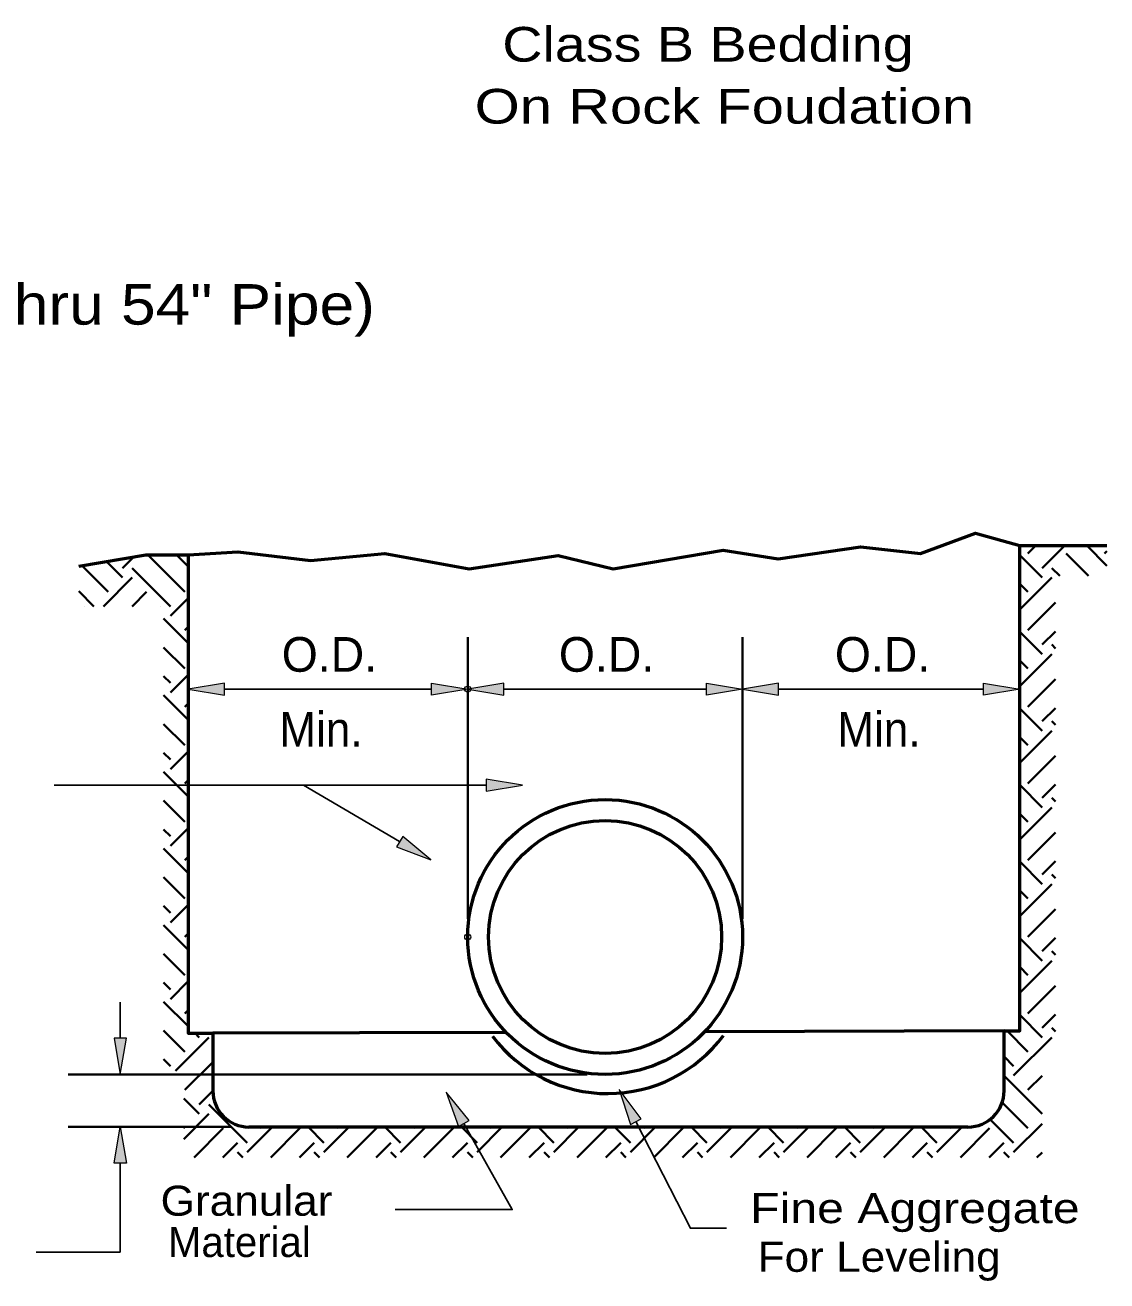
# Model space of a CAD drawing. Extents: x 36.1 to 71.5, y 0.2 to 22.2.
# Drawn here: x 46.27 to 51.06, y 10.72 to 16.28 of the extents above; entities that cross this region are included whole.
import ezdxf

# ---------------------------------------------------------------- set-up
doc = ezdxf.new("R2010")
doc.units = 0
doc.header["$LTSCALE"] = 0.053
doc.header["$PDMODE"] = 32
doc.header["$PDSIZE"] = 0.0265
for name, color, linetype, lineweight in [('1', 7, 'Continuous', 35), ('3', 7, 'Continuous', 25), ('6', 7, 'Continuous', 13)]:
    doc.layers.add(name, color=color, linetype=linetype, lineweight=lineweight)

msp = doc.modelspace()

# ---------------------------------------------------------------- hatches: boundary and pattern name
at = {"layer": '1'}
for points in [[(47.14958, 13.31667), (47.14958, 13.37), (46.98958, 13.34325), (46.98958, 13.34325)], [(48.06725, 13.31667), (48.06725, 13.37), (48.22725, 13.34325), (48.22725, 13.34325)], [(48.38725, 13.31667), (48.38725, 13.37), (48.22725, 13.34325), (48.22725, 13.34325)], [(49.2845, 13.31667), (49.2845, 13.37), (49.4445, 13.34325), (49.4445, 13.34325)], [(49.6045, 13.31667), (49.6045, 13.37), (49.4445, 13.34325), (49.4445, 13.34325)], [(50.51225, 13.31667), (50.51225, 13.37), (50.67225, 13.34325), (50.67225, 13.34325)]]:
    msp.add_hatch(color=256, dxfattribs=at).paths.add_polyline_path(points)
at = {"layer": '3'}
for points in [[(48.30958, 12.94433), (48.30958, 12.891), (48.46958, 12.91767), (48.46958, 12.91767)], [(47.93925, 12.69067), (47.91225, 12.64467), (48.06383, 12.5865), (48.06383, 12.5865)], [(46.71525, 11.79633), (46.66192, 11.79633), (46.68858, 11.63633), (46.68858, 11.63633)], [(48.18667, 11.40533), (48.23317, 11.4315), (48.13142, 11.55775), (48.13142, 11.55775)], [(48.94775, 11.41517), (48.99508, 11.4395), (48.89858, 11.56967), (48.89858, 11.56967)], [(46.71525, 11.24342), (46.66192, 11.24342), (46.68858, 11.40342), (46.68858, 11.40342)]]:
    msp.add_hatch(color=256, dxfattribs=at).paths.add_polyline_path(points)

# ---------------------------------------------------------------- linework, layer by layer
at = {"layer": '1'}
for p, q in [((50.70817, 13.94325), (50.74433, 13.97942)), ((50.77183, 13.8795), (50.87167, 13.97942)), ((51.05833, 13.89), (50.96908, 13.97942)), ((46.69892, 13.83717), (46.62742, 13.90858)), ((46.69892, 13.8795), (46.74817, 13.92883)), ((46.97475, 13.7735), (46.81033, 13.93783)), ((46.98958, 13.88583), (46.93758, 13.93783)), ((50.77183, 13.83717), (50.67225, 13.93675)), ((50.97675, 13.84433), (50.87792, 13.94325)), ((51.04758, 13.94325), (51.05833, 13.95392)), ((46.63525, 13.7735), (46.51842, 13.89033)), ((46.911, 13.70983), (46.74133, 13.8795)), ((50.8495, 13.84433), (50.81425, 13.8795)), ((46.61342, 13.70933), (46.74133, 13.83717)), ((50.67225, 13.69517), (50.81425, 13.83717)), ((50.70817, 13.7735), (50.67225, 13.8095)), ((46.57158, 13.70983), (46.50442, 13.77692)), ((46.74083, 13.70933), (46.805, 13.7735)), ((46.911, 13.66742), (46.98958, 13.74592)), ((46.52858, 13.70933), (46.52917, 13.70983)), ((46.86808, 13.70933), (46.86858, 13.70983)), ((50.70817, 13.60383), (50.83058, 13.72625)), ((46.98958, 13.5465), (46.88058, 13.65533)), ((46.97475, 13.60383), (46.98958, 13.61867)), ((48.22725, 12.325), (48.22725, 13.57375)), ((49.4445, 12.325), (49.4445, 13.57375)), ((50.77183, 13.49767), (50.67225, 13.59733)), ((50.77183, 13.54017), (50.83058, 13.59892)), ((46.97475, 13.43417), (46.88058, 13.52808)), ((50.83058, 13.52375), (50.81425, 13.54017)), ((50.67225, 13.35575), (50.81425, 13.49767)), ((50.70817, 13.43417), (50.67225, 13.47008)), ((46.911, 13.3705), (46.88058, 13.40083)), ((46.911, 13.328), (46.98958, 13.4065)), ((50.70817, 13.26442), (50.83058, 13.38683)), ((46.98958, 13.207), (46.88058, 13.31592)), ((46.97475, 13.26442), (46.98958, 13.27925)), ((50.77183, 13.15825), (50.67225, 13.25792)), ((50.77183, 13.20075), (50.83058, 13.2595)), ((46.97475, 13.09475), (46.88058, 13.18867)), ((50.83058, 13.18433), (50.81425, 13.20075)), ((50.67225, 13.01633), (50.81425, 13.15825)), ((50.70817, 13.09475), (50.67225, 13.13067)), ((46.911, 13.031), (46.88058, 13.06142)), ((46.911, 12.98858), (46.98958, 13.06708)), ((50.70817, 12.925), (50.83058, 13.0475)), ((46.98958, 12.86758), (46.88058, 12.9765)), ((46.97475, 12.925), (46.98958, 12.93983)), ((50.77183, 12.81883), (50.67225, 12.9185)), ((50.77183, 12.86133), (50.83058, 12.92008)), ((50.83058, 12.84483), (50.81425, 12.86133)), ((46.97475, 12.75525), (46.88058, 12.84925)), ((50.67225, 12.67683), (50.81425, 12.81883)), ((50.70817, 12.75525), (50.67225, 12.79125)), ((46.911, 12.69158), (46.88058, 12.722)), ((46.911, 12.64917), (46.98958, 12.72767)), ((50.70817, 12.58558), (50.83058, 12.70808)), ((46.98958, 12.52817), (46.88058, 12.63717)), ((46.98958, 12.52817), (46.88058, 12.63717)), ((46.97475, 12.58558), (46.98958, 12.60042)), ((50.77183, 12.4795), (50.67225, 12.57908)), ((50.77183, 12.52192), (50.83058, 12.58067)), ((50.83058, 12.5055), (50.81425, 12.52192)), ((46.97475, 12.41583), (46.88058, 12.50983)), ((50.67225, 12.3375), (50.81425, 12.4795)), ((50.67225, 12.3375), (50.81425, 12.4795)), ((50.70817, 12.41583), (50.67225, 12.45183)), ((46.911, 12.35217), (46.88058, 12.38258)), ((46.911, 12.30975), (46.98958, 12.38825)), ((50.70817, 12.24617), (50.83058, 12.36858)), ((46.98958, 12.18883), (46.88058, 12.29767)), ((46.97475, 12.24617), (46.98958, 12.261)), ((50.77183, 12.14008), (50.67225, 12.23967)), ((50.77183, 12.1825), (50.83058, 12.24125)), ((46.97475, 12.0765), (46.88058, 12.1705)), ((50.67225, 11.99808), (50.81425, 12.14008)), ((50.83058, 12.16608), (50.81425, 12.1825)), ((50.70817, 12.0765), (50.67225, 12.11242)), ((46.911, 12.01283), (46.88058, 12.04317)), ((46.911, 11.97033), (46.98958, 12.04892)), ((50.70817, 11.90675), (50.83058, 12.02917)), ((46.98958, 11.84942), (46.88058, 11.95825)), ((46.97475, 11.90675), (46.98958, 11.92158)), ((50.77183, 11.80058), (50.67225, 11.90025)), ((50.77183, 11.84308), (50.83058, 11.90183)), ((46.97475, 11.73708), (46.88058, 11.831)), ((46.93283, 11.65267), (47.08075, 11.80058)), ((47.03825, 11.80058), (47.02008, 11.81883)), ((50.70817, 11.73708), (50.616, 11.82917)), ((50.64458, 11.63092), (50.81425, 11.80058)), ((50.83058, 11.82675), (50.81425, 11.84308)), ((46.911, 11.67342), (46.88058, 11.70383)), ((46.97475, 11.56733), (47.0985, 11.69108)), ((50.64458, 11.67342), (50.603, 11.715)), ((50.77125, 11.46183), (50.603, 11.63017)), ((50.70817, 11.56733), (50.77125, 11.63042)), ((47.03825, 11.46117), (46.96967, 11.52983)), ((47.03825, 11.50367), (47.0985, 11.56383)), ((46.96967, 11.35025), (47.08075, 11.46117)), ((47.2505, 11.33392), (47.08075, 11.50367)), ((50.70817, 11.39767), (50.59433, 11.5115)), ((50.64458, 11.33392), (50.54133, 11.43717)), ((50.64458, 11.2915), (50.77125, 11.41817)), ((46.97475, 11.39767), (46.96967, 11.4025)), ((47.01517, 11.26833), (47.14442, 11.39767)), ((47.2505, 11.2915), (47.36233, 11.40342)), ((47.31417, 11.39767), (47.30825, 11.40342)), ((47.35458, 11.26833), (47.48383, 11.39767)), ((47.58992, 11.33392), (47.52042, 11.40342)), ((47.58992, 11.2915), (47.70167, 11.40342)), ((47.65358, 11.39767), (47.64767, 11.40342)), ((47.69392, 11.26833), (47.82325, 11.39767)), ((47.92925, 11.33392), (47.85983, 11.40342)), ((47.92925, 11.2915), (48.04108, 11.40342)), ((47.99292, 11.39767), (47.98708, 11.40342)), ((48.03342, 11.26833), (48.16258, 11.39767)), ((48.26867, 11.33392), (48.19925, 11.40342)), ((48.26867, 11.2915), (48.3805, 11.40342)), ((48.33225, 11.39767), (48.3265, 11.40342)), ((48.37283, 11.26833), (48.50192, 11.39767)), ((48.60808, 11.33392), (48.53867, 11.40342)), ((48.60808, 11.2915), (48.71992, 11.40342)), ((48.67167, 11.39767), (48.66592, 11.40342)), ((48.71225, 11.26833), (48.84142, 11.39767)), ((48.94758, 11.33392), (48.87808, 11.40342)), ((48.94758, 11.2915), (49.05925, 11.40342)), ((49.01108, 11.39767), (49.00533, 11.40342)), ((49.05158, 11.26833), (49.18083, 11.39767)), ((49.28692, 11.33392), (49.2175, 11.40342)), ((49.28692, 11.2915), (49.39875, 11.40342)), ((49.3505, 11.39767), (49.34475, 11.40342)), ((49.391, 11.26833), (49.52025, 11.39767)), ((49.62633, 11.33392), (49.55692, 11.40342)), ((49.62633, 11.2915), (49.73817, 11.40342)), ((49.68992, 11.39767), (49.68417, 11.40342)), ((49.7305, 11.26833), (49.85958, 11.39767)), ((49.96575, 11.33392), (49.89633, 11.40342)), ((49.96575, 11.2915), (50.07758, 11.40342)), ((50.02933, 11.39767), (50.02358, 11.40342)), ((50.06992, 11.26833), (50.199, 11.39767)), ((50.30517, 11.33392), (50.23575, 11.40342)), ((50.30517, 11.2915), (50.41692, 11.40342)), ((50.36875, 11.39767), (50.363, 11.40342)), ((50.40925, 11.26833), (50.5385, 11.39767)), ((47.14242, 11.26833), (47.208, 11.33392)), ((47.48183, 11.26833), (47.54742, 11.33392)), ((47.82125, 11.26833), (47.88683, 11.33392)), ((48.16058, 11.26833), (48.22625, 11.33392)), ((48.50008, 11.26833), (48.56567, 11.33392)), ((48.8395, 11.26833), (48.90508, 11.33392)), ((49.17892, 11.26833), (49.2445, 11.33392)), ((49.51825, 11.26833), (49.58392, 11.33392)), ((49.85767, 11.26833), (49.92325, 11.33392)), ((50.19717, 11.26833), (50.26275, 11.33392)), ((50.53658, 11.26833), (50.60217, 11.33392)), ((47.23117, 11.26833), (47.208, 11.2915)), ((47.57058, 11.26833), (47.54742, 11.2915)), ((47.90992, 11.26833), (47.88683, 11.2915)), ((48.24942, 11.26833), (48.22625, 11.2915)), ((48.58883, 11.26833), (48.56567, 11.2915)), ((48.92825, 11.26833), (48.90508, 11.2915)), ((49.26758, 11.26833), (49.2445, 11.2915)), ((49.607, 11.26833), (49.58392, 11.2915)), ((49.9465, 11.26833), (49.92325, 11.2915)), ((50.28592, 11.26833), (50.26275, 11.2915)), ((50.62525, 11.26833), (50.60217, 11.2915)), ((50.74867, 11.26833), (50.77125, 11.291))]:
    msp.add_line(p, q, dxfattribs=at)
at = {"layer": '1', "lineweight": 13}
for p, q in [((48.22725, 12.325), (48.22725, 13.57375)), ((49.4445, 12.325), (49.4445, 13.57375)), ((50.67225, 13.39967), (50.67225, 13.57375)), ((46.98958, 13.26333), (46.98958, 13.11292))]:
    msp.add_line(p, q, dxfattribs=at)
at = {"layer": '1', "lineweight": 25}
for p, q in [((47.14958, 13.34333), (48.06725, 13.34333)), ((48.38725, 13.34333), (49.2845, 13.34333)), ((49.6045, 13.34333), (50.51225, 13.34333))]:
    msp.add_line(p, q, dxfattribs=at)
at = {"layer": '1', "lineweight": 53}
for p, q in [((48.39767, 11.82275), (47.0985, 11.81883)), ((50.603, 11.82917), (49.2765, 11.82542)), ((47.2585, 11.40342), (50.443, 11.40342))]:
    msp.add_line(p, q, dxfattribs=at)
for points in [[(46.98958, 13.93783), (47.20858, 13.95092), (47.53108, 13.91325), (47.86083, 13.94333), (48.23342, 13.87575), (48.62758, 13.93583), (48.87125, 13.87575), (49.3585, 13.95842), (49.60225, 13.92083), (49.96767, 13.97342), (50.23292, 13.94333), (50.4765, 14.03358), (50.67225, 13.97942)], [(50.603, 11.56342), (50.603, 11.82917), (50.67225, 11.82917), (50.67225, 13.97942), (51.05833, 13.97942)], [(46.50442, 13.888), (46.8015, 13.93783), (46.98958, 13.93783), (46.98958, 11.81883), (47.0985, 11.81883), (47.0985, 11.56342)]]:
    msp.add_lwpolyline(points, dxfattribs=at)
at = {"layer": '1', "lineweight": 13}
for points in [[(47.14958, 13.31667), (47.14958, 13.37), (46.98958, 13.34325), (46.98958, 13.34325)], [(48.06725, 13.31667), (48.06725, 13.37), (48.22725, 13.34325), (48.22725, 13.34325)], [(48.38725, 13.31667), (48.38725, 13.37), (48.22725, 13.34325), (48.22725, 13.34325)], [(49.2845, 13.31667), (49.2845, 13.37), (49.4445, 13.34325), (49.4445, 13.34325)], [(49.6045, 13.31667), (49.6045, 13.37), (49.4445, 13.34325), (49.4445, 13.34325)], [(50.51225, 13.31667), (50.51225, 13.37), (50.67225, 13.34325), (50.67225, 13.34325)]]:
    msp.add_lwpolyline(points, close=True, dxfattribs=at)
at = {"layer": '1', "lineweight": 53}
for radius in [0.60865, 0.51601]:
    msp.add_circle((48.83584, 12.24511), radius, dxfattribs=at)
for centre, radius, start, end in [((48.84725, 12.1908), 0.63944, 217.05519, 323.28444), ((47.25846, 11.5634), 0.16, 180, 270), ((50.44299, 11.5634), 0.16, 270, 0)]:
    msp.add_arc(centre, radius, start, end, dxfattribs=at)
at = {"layer": '3'}
for p, q in [((48.30958, 12.91767), (46.39558, 12.91767)), ((47.92575, 12.66758), (47.50017, 12.91767)), ((46.68858, 11.7965), (46.68858, 11.9565)), ((46.68858, 11.24342), (46.68858, 10.84958)), ((46.68858, 10.84958), (46.31525, 10.84958))]:
    msp.add_line(p, q, dxfattribs=at)
at = {"layer": '3', "lineweight": 35}
for p, q in [((48.75583, 11.6365), (46.45825, 11.6365)), ((47.1785, 11.40342), (46.45825, 11.40342))]:
    msp.add_line(p, q, dxfattribs=at)
at = {"layer": '3', "lineweight": 13}
msp.add_line((46.68858, 11.40342), (46.68875, 11.40342), dxfattribs=at)
for points in [[(48.30958, 12.94433), (48.30958, 12.891), (48.46958, 12.91767), (48.46958, 12.91767)], [(47.93925, 12.69067), (47.91225, 12.64467), (48.06383, 12.5865), (48.06383, 12.5865)], [(46.71525, 11.79633), (46.66192, 11.79633), (46.68858, 11.63633), (46.68858, 11.63633)], [(48.18667, 11.40533), (48.23317, 11.4315), (48.13142, 11.55775), (48.13142, 11.55775)], [(48.94775, 11.41517), (48.99508, 11.4395), (48.89858, 11.56967), (48.89858, 11.56967)], [(46.71525, 11.24342), (46.66192, 11.24342), (46.68858, 11.40342), (46.68858, 11.40342)]]:
    msp.add_lwpolyline(points, close=True, dxfattribs=at)
at = {"layer": '3'}
for points in [[(48.20992, 11.4185), (48.42442, 11.0375), (47.90592, 11.0375)], [(48.97158, 11.42725), (49.21342, 10.95475), (49.37342, 10.95475)]]:
    msp.add_lwpolyline(points, dxfattribs=at)
at = {"layer": '6'}
for p, q in [((46.98958, 13.34333), (46.98967, 13.34333)), ((49.4445, 13.34333), (49.44458, 13.34333)), ((50.67225, 13.34333), (50.67233, 13.34333)), ((50.67225, 13.31967), (50.67233, 13.31967)), ((49.30283, 12.437), (49.30292, 12.437)), ((49.4445, 12.245), (49.44458, 12.245)), ((49.4445, 12.245), (49.44458, 12.245)), ((48.34967, 12.04117), (48.34975, 12.04117)), ((48.83583, 11.6365), (48.83592, 11.6365)), ((47.2585, 11.40342), (47.25858, 11.40342))]:
    msp.add_line(p, q, dxfattribs=at)
for p in [(48.22725, 13.34333), (48.22725, 12.245)]:
    msp.add_point(p, dxfattribs=at)

# ---------------------------------------------------------------- texts
at = {"layer": '1'}
for p in [(47.40358, 13.42017), (48.631, 13.42017), (49.85342, 13.42017)]:
    msp.add_text('O.D.', height=0.1536, dxfattribs=at).set_placement(p)
at = {"layer": '3'}
for s, height, width, p in [('Class B Bedding', 0.1536, 1.2, (48.3805, 16.12292)), ('On Rock Foudation', 0.1536, 1.25, (48.25808, 15.84842)), ('(Trench shown is for 18" thru 54" Pipe)', 0.1792, 1.15, (43.08658, 14.95792)), ('Min.', 0.1536, 0.95, (47.39292, 13.08833)), ('Min.', 0.1536, 0.95, (49.86442, 13.08833)), ('Granular', 0.133, 1.1, (46.86692, 11.01033)), ('Fine Aggregate', 0.133, 1.2, (49.47842, 10.9775)), ('For Leveling', 0.133, 1.1, (49.51125, 10.76183))]:
    msp.add_text(s, height=height, dxfattribs=dict(at, width=width)).set_placement(p)
msp.add_text('Material', height=0.133, dxfattribs=at).set_placement((46.89967, 10.82742))

doc.saveas('drawing.dxf')
